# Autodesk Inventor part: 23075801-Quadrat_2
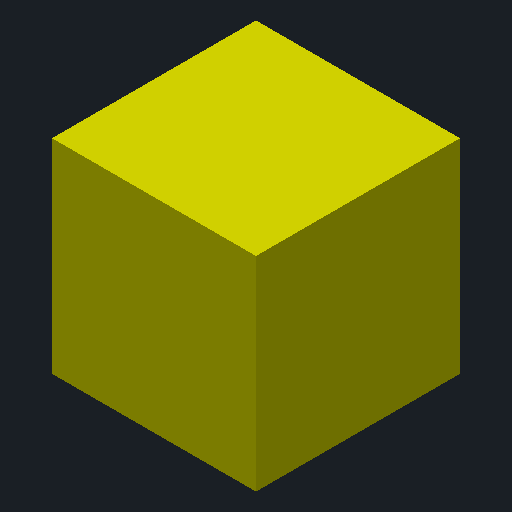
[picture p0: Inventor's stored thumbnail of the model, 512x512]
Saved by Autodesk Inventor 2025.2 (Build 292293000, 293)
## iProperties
Company: Ed. Züblin AG
RuleStatus: InUse
Created: 2025-03
Part Number: 23075801-Quadrat_2
Material: Stahlbeton C30/37
Document SubType Name: Modeling
Designer: FrodlSte
Mass: 2.5e+06 g
Surface Area: 60000 cm^2
Volume: 1e+06 cm^3
Density: 2.5 g/cm^3
Appearance: Beton C30/37
Description: Ausbruch
z_Bereich: Tunnelbau
z_Direktion: Tief- und Tunnelbau
z_Konzerneinheit: Zentrale Technik
z_Matchkey: =<z_Matchkey_010>_<z_Matchkey_020>_<z_Matchkey_030>_<z_Matchkey_040>_<z_Matchkey_050>_<z_Matchkey_060>_<z_Matchkey_070>_<z_Matchkey_080>_<z_Matchkey_090>_<z_Mat
cpiComponentType: Attribut
cpiFitMatchkey: =<z_Matchkey>
z_Matchkey_010: xxxxx
z_Matchkey_020: 5DTUB
z_Matchkey_030: xxx
z_Matchkey_040: xxx
z_Matchkey_050: xxx
z_Matchkey_060: xxx
z_Matchkey_070: xxx
z_Matchkey_080: xxx
z_Matchkey_090: xxx
z_Matchkey_100: xxx
z_Matchkey_110: xxx
z_Matchkey_120: xxxxxxx
z_Matchkey_130: SOHL
z_Matchkey_140: xxxx
DocNumber: 23075801-Quadrat_2.ipt
Folder: DL23075801-DE-Pfaffensteigtunnel\BIM\Testmodell
VDS_Category: 09 - BIM - Konstruktion
DBSet_Element:010_Eigentuemer: DBE
DBSet_Element:020_Autor: ND
DBSet_Element:030_Projektnummer: G.016268527
DBSet_Element:040_Bereich: ND
DBSet_Element:050_Vertragspartner: ND
DBSet_Element:060_Gewerk: ND
DBSet_Element:070_Bauwerk: EW
DBSet_Element:080_Bauwerksnummer: 17030
DBSet_Element:090_Bezeichnung: ND
DBSet_Element:100_Gruppe: Ausbruch
DBSet_Element:110_Element: Ausbruch
DBSet_Element:120_Elementtyp: Kalotte
DBSet_Element:130_Identifikationsnummer: ND
DBSet_Element:140_Position_1: KALO
DBSet_Element:150_Position_2: FIRS
DBSet_Element:160_PUID: ND
DBSet_Element:170_Hauptmaterialitaet: ND
DBSet_Element:171_Materialindikator_1: ND
DBSet_Element:172_Materialindikator_2: ND
DBSet_Geometrie:Flaeche: -99999.0
DBSet_Geometrie:Laenge: -99999.0
DBSet_Geometrie:Volumen_Solid: 7.21
DBSet_Position:Streckenachse: ND
DBSet_Position:Streckenkilometer_Anfang: -99999
DBSet_Position:Streckenkilometer_Ende: -99999
DBSet_Position:Tunnelachse: ND
DBSet_Position:Tunnelmeter_Anfang: -99999
DBSet_Position:Tunnelmeter_Ende: -99999
DBSet_TP:Status: ABB
DBSet_TU_Ausbruch:Abrasivitaetsindex: 0.4
DBSet_TU_Ausbruch:Abrechnungsquerschnitt: -99999.0
DBSet_TU_Ausbruch:Abschlagslaenge: -99999.0
DBSet_TU_Ausbruch:Ausfuehrungsrichtung: fallend
DBSet_TU_Ausbruch:Grenzwassermenge: bis_0,5l/s
DBSet_TU_Ausbruch:Homogenbereich: 1
DBSet_TU_Ausbruch:Modus: ND
DBSet_TU_Ausbruch:Stuetzmittel: Druckluft
DBSet_TU_Ausbruch:ta_cm: 30
DBSet_TU_Ausbruch:tb_cm: 100
DBSet_TU_Ausbruch:td_cm: 300
DBSet_TU_Ausbruch:ti_cm: 300
DBSet_TU_Ausbruch:ue_cm: 400
DBSet_TU_Ausbruch:Vortriebsabschnitt: N-1.1
DBSet_TU_Ausbruch:Vortriebsklasse: ND
DBSet_TU_Ausbruch:Wasserzufluss: 0-3
z_DBSet_Element:010_Eigentuemer: DBInfraGo
z_DBSet_Element:020_Autor: Vertragspartner 2 ZB
z_DBSet_Element:030_Projektnummer: Gaeubahn Nord HP Goldberg (DBnfraGO, BK11)
z_DBSet_Element:040_Bereich: PFA 1 Tunnel
z_DBSet_Element:050_Vertragspartner: Tunnel
z_DBSet_Element:060_Gewerk: Tunnelbau
z_DBSet_Element:070_Bauwerk: SBW-Tu
z_DBSet_Element:080_Bauwerksnummer: zzz (leer)
z_DBSet_Element:090_Bezeichnung: zzz (leer)
z_DBSet_Element:100_Gruppe: Ausbruch
z_DBSet_Element:110_Element: Ausbruch
z_DBSet_Element:120_Elementtyp: Sohle
z_DBSet_Element:130_Identifikationsnummer: nicht definiert
z_DBSet_Element:140_Position_1: Sohle
z_DBSet_Element:150_Position_2: Nicht definiert
z_DBSet_Element:160_PUID: nicht definiert
z_DBSet_Element:170_Hauptmaterialitaet: nicht definiert
z_DBSet_Element:171_Materialindikator_1: nicht definiert
z_DBSet_Element:172_Materialindikator_2: nicht definiert
z_DBSet_Geometrie:Flaeche: 1,000 m^2
z_DBSet_Geometrie:Laenge: -99999,000 m
z_DBSet_Position:Streckenachse: zzz (leer)
z_DBSet_Position:Streckenkilometer_Anfang: -11111,000 oE
z_DBSet_Position:Streckenkilometer_Ende: -11111,000 oE
z_DBSet_Position:Tunnelachse: zzz (leer)
z_DBSet_Position:Tunnelmeter_Anfang: -11111,000 oE
z_DBSet_Position:Tunnelmeter_Ende: -11111,000 oE
z_DBSet_TP:Status: Neubau
z_DBSet_TU_Ausbruch:Abrasivitaetsindex: zzz (leer)
z_DBSet_TU_Ausbruch:Abrechnungsquerschnitt: -99999,000 m^2
z_DBSet_TU_Ausbruch:Abschlagslaenge: 2,000 m
z_DBSet_TU_Ausbruch:Ausfuehrungsrichtung: zzz (leer)
z_DBSet_TU_Ausbruch:Grenzwassermenge: zzz (leer)
z_DBSet_TU_Ausbruch:Homogenbereich: zzz (leer)
z_DBSet_TU_Ausbruch:Modus: Abbaukammer vollstaendig gefuellt
z_DBSet_TU_Ausbruch:Stuetzmittel: Nicht definiert
z_DBSet_TU_Ausbruch:Vortriebsabschnitt: zzz (leer)
z_DBSet_TU_Ausbruch:Vortriebsklasse: zzz (leer)
z_DBSet_TU_Ausbruch:Wasserzufluss: zzz (leer)
z_DBSet_Geometrie:Volumen_Solid: -11111,000 m^3
z_DBSet_TU_Ausbruch:ta_cm: 30,000 cm
z_DBSet_TU_Ausbruch:tb_cm: 100,000 cm
z_DBSet_TU_Ausbruch:td_cm: 300,000 cm
z_DBSet_TU_Ausbruch:ti_cm: 300,000 cm
z_DBSet_TU_Ausbruch:ue_cm: 400,000 cm
Author: FrodlSte
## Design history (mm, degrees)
derived "23075801-Skelett.ipt"
node "Quadrat_2"
node "Volumenkörpern"
node "Oberflächenkörpern"
feature "Quadrat_2::23075801-Skelett.ipt" dims "d4" = 10
tag "Bezeichnung1"
other parameters: "Ausbruchsfläche_Sohle_Area" = 100000 [user parameter; used in 1 equation term]
